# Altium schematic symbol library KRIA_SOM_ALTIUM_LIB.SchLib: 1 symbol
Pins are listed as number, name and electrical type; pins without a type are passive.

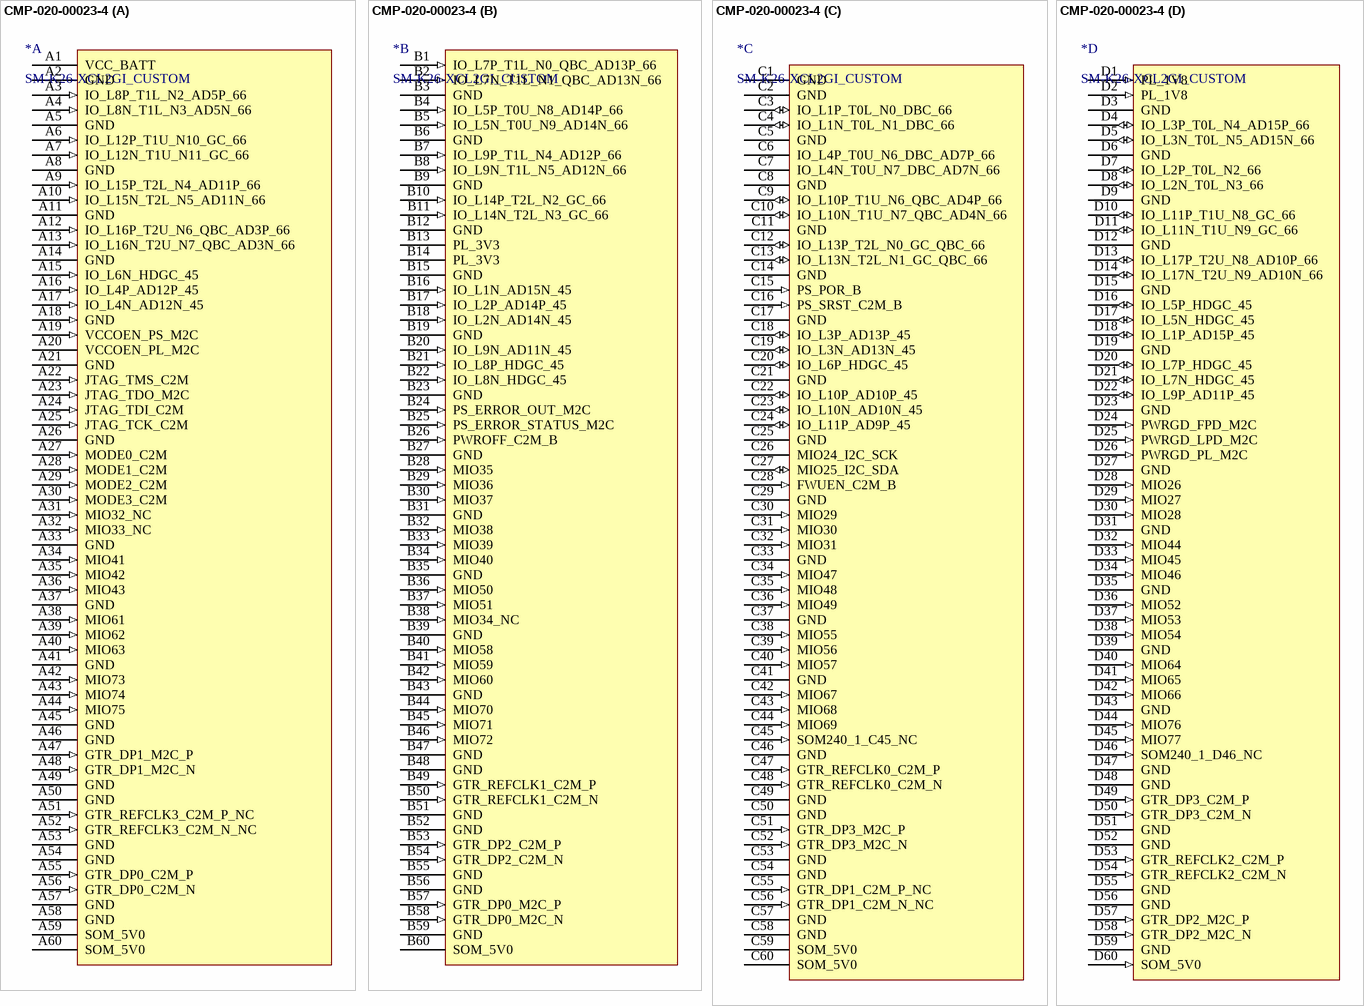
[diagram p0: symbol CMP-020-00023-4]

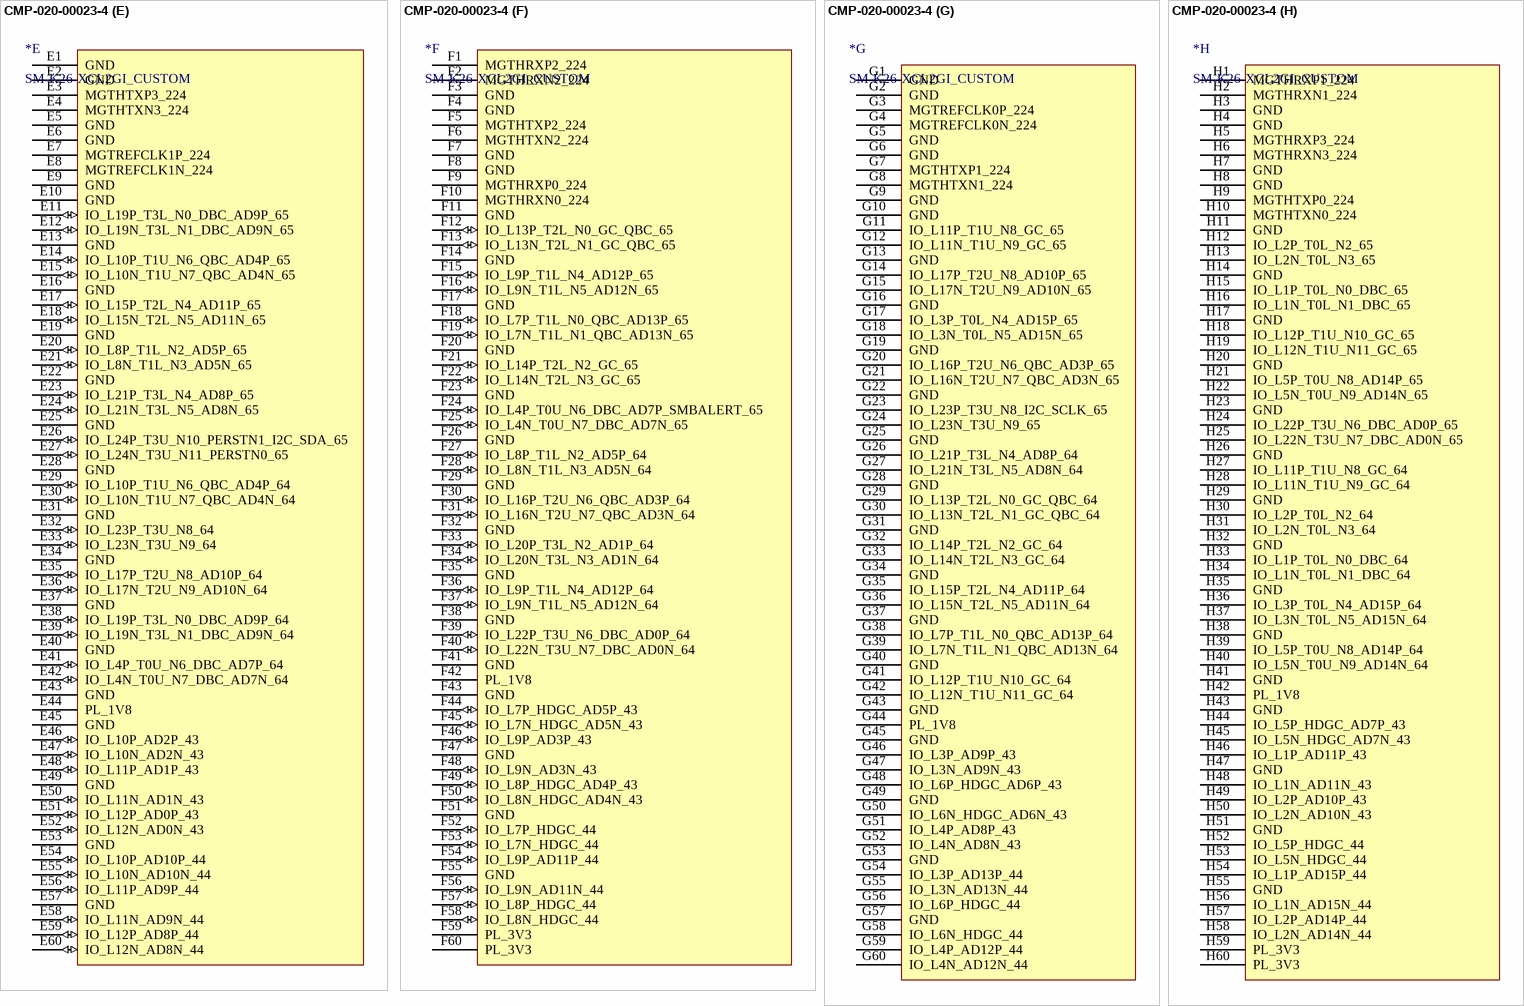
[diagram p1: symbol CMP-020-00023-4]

## CMP-020-00023-4
designator *, comment SM-K26-XCL2GI_CUSTOM
Zynq UltraScale Kria Embedded Module ARM Cortex-A53 Arm Cortex-R5F 533MHz, 1.333GHz 4GB 16GB eMMC, 64MB QSPI. Just the schematic is custom, Footprint already took from SnapMagic
footprint SM-K26-XCL2GI_CUSTOM-Footprint-1
part A pins: A1 VCC_BATT, A2 GND, A3 IO_L8P_T1L_N2_AD5P_66 (in), A4 IO_L8N_T1L_N3_AD5N_66 (in), A5 GND, A6 IO_L12P_T1U_N10_GC_66 (in), A7 IO_L12N_T1U_N11_GC_66 (in), A8 GND, A9 IO_L15P_T2L_N4_AD11P_66 (in), A10 IO_L15N_T2L_N5_AD11N_66 (in), A11 GND, A12 IO_L16P_T2U_N6_QBC_AD3P_66 (in), A13 IO_L16N_T2U_N7_QBC_AD3N_66 (in), A14 GND, A15 IO_L6N_HDGC_45 (in), A16 IO_L4P_AD12P_45 (in), A17 IO_L4N_AD12N_45 (in), A18 GND (in), A19 VCCOEN_PS_M2C (in), A20 VCCOEN_PL_M2C, A21 GND, A22 JTAG_TMS_C2M (in), A23 JTAG_TDO_M2C (in), A24 JTAG_TDI_C2M (in), A25 JTAG_TCK_C2M (in), A26 GND, A27 MODE0_C2M (in), A28 MODE1_C2M (in), A29 MODE2_C2M (in), A30 MODE3_C2M (in), A31 MIO32_NC (in), A32 MIO33_NC (in), A33 GND, A34 MIO41 (in), A35 MIO42 (in), A36 MIO43 (in), A37 GND, A38 MIO61 (in), A39 MIO62 (in), A40 MIO63 (in), A41 GND, A42 MIO73 (in), A43 MIO74 (in), A44 MIO75 (in), A45 GND, A46 GND, A47 GTR_DP1_M2C_P (in), A48 GTR_DP1_M2C_N (in), A49 GND, A50 GND, A51 GTR_REFCLK3_C2M_P_NC (in), A52 GTR_REFCLK3_C2M_N_NC (in), A53 GND, A54 GND, A55 GTR_DP0_C2M_P (in), A56 GTR_DP0_C2M_N (in), A57 GND, A58 GND, A59 SOM_5V0, A60 SOM_5V0
part B pins: B1 IO_L7P_T1L_N0_QBC_AD13P_66 (in), B2 IO_L7N_T1L_N1_QBC_AD13N_66 (in), B3 GND, B4 IO_L5P_T0U_N8_AD14P_66 (in), B5 IO_L5N_T0U_N9_AD14N_66 (in), B6 GND, B7 IO_L9P_T1L_N4_AD12P_66 (in), B8 IO_L9N_T1L_N5_AD12N_66 (in), B9 GND, B10 IO_L14P_T2L_N2_GC_66 (in), B11 IO_L14N_T2L_N3_GC_66 (in), B12 GND, B13 PL_3V3, B14 PL_3V3, B15 GND, B16 IO_L1N_AD15N_45 (in), B17 IO_L2P_AD14P_45 (in), B18 IO_L2N_AD14N_45 (in), B19 GND, B20 IO_L9N_AD11N_45 (in), B21 IO_L8P_HDGC_45 (in), B22 IO_L8N_HDGC_45 (in), B23 GND, B24 PS_ERROR_OUT_M2C (in), B25 PS_ERROR_STATUS_M2C (in), B26 PWROFF_C2M_B (in), B27 GND, B28 MIO35 (in), B29 MIO36 (in), B30 MIO37 (in), B31 GND, B32 MIO38 (in), B33 MIO39 (in), B34 MIO40 (in), B35 GND, B36 MIO50 (in), B37 MIO51 (in), B38 MIO34_NC (in), B39 GND, B40 MIO58 (in), B41 MIO59 (in), B42 MIO60 (in), B43 GND, B44 MIO70 (in), B45 MIO71 (in), B46 MIO72 (in), B47 GND, B48 GND, B49 GTR_REFCLK1_C2M_P (in), B50 GTR_REFCLK1_C2M_N (in), B51 GND, B52 GND, B53 GTR_DP2_C2M_P (in), B54 GTR_DP2_C2M_N (in), B55 GND, B56 GND, B57 GTR_DP0_M2C_P (in), B58 GTR_DP0_M2C_N (in), B59 GND, B60 SOM_5V0
part C pins: C1 GND, C2 GND, C3 IO_L1P_T0L_N0_DBC_66 (io), C4 IO_L1N_T0L_N1_DBC_66 (io), C5 GND, C6 IO_L4P_T0U_N6_DBC_AD7P_66, C7 IO_L4N_T0U_N7_DBC_AD7N_66, C8 GND, C9 IO_L10P_T1U_N6_QBC_AD4P_66 (io), C10 IO_L10N_T1U_N7_QBC_AD4N_66 (io), C11 GND, C12 IO_L13P_T2L_N0_GC_QBC_66 (io), C13 IO_L13N_T2L_N1_GC_QBC_66 (io), C14 GND, C15 PS_POR_B (in), C16 PS_SRST_C2M_B (in), C17 GND, C18 IO_L3P_AD13P_45 (io), C19 IO_L3N_AD13N_45 (io), C20 IO_L6P_HDGC_45 (io), C21 GND, C22 IO_L10P_AD10P_45 (io), C23 IO_L10N_AD10N_45 (io), C24 IO_L11P_AD9P_45 (io), C25 GND, C26 MIO24_I2C_SCK, C27 MIO25_I2C_SDA (io), C28 FWUEN_C2M_B (in), C29 GND, C30 MIO29 (in), C31 MIO30 (in), C32 MIO31 (in), C33 GND, C34 MIO47 (in), C35 MIO48 (in), C36 MIO49 (in), C37 GND, C38 MIO55 (in), C39 MIO56 (in), C40 MIO57 (in), C41 GND, C42 MIO67 (in), C43 MIO68 (in), C44 MIO69 (in), C45 SOM240_1_C45_NC (in), C46 GND, C47 GTR_REFCLK0_C2M_P (in), C48 GTR_REFCLK0_C2M_N (in), C49 GND, C50 GND, C51 GTR_DP3_M2C_P (in), C52 GTR_DP3_M2C_N (in), C53 GND, C54 GND, C55 GTR_DP1_C2M_P_NC (in), C56 GTR_DP1_C2M_N_NC (in), C57 GND, C58 GND, C59 SOM_5V0, C60 SOM_5V0
part D pins: D1 PL_1V8 (in), D2 PL_1V8 (in), D3 GND, D4 IO_L3P_T0L_N4_AD15P_66 (io), D5 IO_L3N_T0L_N5_AD15N_66 (io), D6 GND, D7 IO_L2P_T0L_N2_66 (io), D8 IO_L2N_T0L_N3_66 (io), D9 GND, D10 IO_L11P_T1U_N8_GC_66 (io), D11 IO_L11N_T1U_N9_GC_66 (io), D12 GND, D13 IO_L17P_T2U_N8_AD10P_66 (io), D14 IO_L17N_T2U_N9_AD10N_66 (io), D15 GND, D16 IO_L5P_HDGC_45 (io), D17 IO_L5N_HDGC_45 (io), D18 IO_L1P_AD15P_45 (io), D19 GND, D20 IO_L7P_HDGC_45 (io), D21 IO_L7N_HDGC_45 (io), D22 IO_L9P_AD11P_45 (io), D23 GND, D24 PWRGD_FPD_M2C (in), D25 PWRGD_LPD_M2C (in), D26 PWRGD_PL_M2C (in), D27 GND, D28 MIO26 (in), D29 MIO27 (in), D30 MIO28 (in), D31 GND, D32 MIO44 (in), D33 MIO45 (in), D34 MIO46 (in), D35 GND, D36 MIO52 (in), D37 MIO53 (in), D38 MIO54 (in), D39 GND, D40 MIO64 (in), D41 MIO65 (in), D42 MIO66 (in), D43 GND, D44 MIO76 (in), D45 MIO77 (in), D46 SOM240_1_D46_NC (in), D47 GND, D48 GND, D49 GTR_DP3_C2M_P (in), D50 GTR_DP3_C2M_N (in), D51 GND, D52 GND, D53 GTR_REFCLK2_C2M_P (in), D54 GTR_REFCLK2_C2M_N (in), D55 GND, D56 GND, D57 GTR_DP2_M2C_P (in), D58 GTR_DP2_M2C_N (in), D59 GND, D60 SOM_5V0 (in)
part E pins: E1 GND, E2 GND, E3 MGTHTXP3_224, E4 MGTHTXN3_224, E5 GND, E6 GND, E7 MGTREFCLK1P_224, E8 MGTREFCLK1N_224, E9 GND, E10 GND, E11 IO_L19P_T3L_N0_DBC_AD9P_65 (io), E12 IO_L19N_T3L_N1_DBC_AD9N_65 (io), E13 GND, E14 IO_L10P_T1U_N6_QBC_AD4P_65 (io), E15 IO_L10N_T1U_N7_QBC_AD4N_65 (io), E16 GND, E17 IO_L15P_T2L_N4_AD11P_65 (io), E18 IO_L15N_T2L_N5_AD11N_65 (io), E19 GND, E20 IO_L8P_T1L_N2_AD5P_65 (io), E21 IO_L8N_T1L_N3_AD5N_65 (io), E22 GND, E23 IO_L21P_T3L_N4_AD8P_65 (io), E24 IO_L21N_T3L_N5_AD8N_65 (io), E25 GND, E26 IO_L24P_T3U_N10_PERSTN1_I2C_SDA_65 (io), E27 IO_L24N_T3U_N11_PERSTN0_65 (io), E28 GND, E29 IO_L10P_T1U_N6_QBC_AD4P_64 (io), E30 IO_L10N_T1U_N7_QBC_AD4N_64 (io), E31 GND, E32 IO_L23P_T3U_N8_64 (io), E33 IO_L23N_T3U_N9_64 (io), E34 GND, E35 IO_L17P_T2U_N8_AD10P_64 (io), E36 IO_L17N_T2U_N9_AD10N_64 (io), E37 GND, E38 IO_L19P_T3L_N0_DBC_AD9P_64 (io), E39 IO_L19N_T3L_N1_DBC_AD9N_64 (io), E40 GND, E41 IO_L4P_T0U_N6_DBC_AD7P_64 (io), E42 IO_L4N_T0U_N7_DBC_AD7N_64 (io), E43 GND, E44 PL_1V8, E45 GND, E46 IO_L10P_AD2P_43 (io), E47 IO_L10N_AD2N_43 (io), E48 IO_L11P_AD1P_43 (io), E49 GND, E50 IO_L11N_AD1N_43 (io), E51 IO_L12P_AD0P_43 (io), E52 IO_L12N_AD0N_43 (io), E53 GND, E54 IO_L10P_AD10P_44 (io), E55 IO_L10N_AD10N_44 (io), E56 IO_L11P_AD9P_44 (io), E57 GND, E58 IO_L11N_AD9N_44 (io), E59 IO_L12P_AD8P_44 (io), E60 IO_L12N_AD8N_44 (io)
part F pins: F1 MGTHRXP2_224, F2 MGTHRXN2_224, F3 GND, F4 GND, F5 MGTHTXP2_224, F6 MGTHTXN2_224, F7 GND, F8 GND, F9 MGTHRXP0_224, F10 MGTHRXN0_224, F11 GND, F12 IO_L13P_T2L_N0_GC_QBC_65 (io), F13 IO_L13N_T2L_N1_GC_QBC_65 (io), F14 GND, F15 IO_L9P_T1L_N4_AD12P_65 (io), F16 IO_L9N_T1L_N5_AD12N_65 (io), F17 GND, F18 IO_L7P_T1L_N0_QBC_AD13P_65 (io), F19 IO_L7N_T1L_N1_QBC_AD13N_65 (io), F20 GND, F21 IO_L14P_T2L_N2_GC_65 (io), F22 IO_L14N_T2L_N3_GC_65 (io), F23 GND, F24 IO_L4P_T0U_N6_DBC_AD7P_SMBALERT_65 (io), F25 IO_L4N_T0U_N7_DBC_AD7N_65 (io), F26 GND, F27 IO_L8P_T1L_N2_AD5P_64 (io), F28 IO_L8N_T1L_N3_AD5N_64 (io), F29 GND, F30 IO_L16P_T2U_N6_QBC_AD3P_64 (io), F31 IO_L16N_T2U_N7_QBC_AD3N_64 (io), F32 GND, F33 IO_L20P_T3L_N2_AD1P_64 (io), F34 IO_L20N_T3L_N3_AD1N_64 (io), F35 GND, F36 IO_L9P_T1L_N4_AD12P_64 (io), F37 IO_L9N_T1L_N5_AD12N_64 (io), F38 GND, F39 IO_L22P_T3U_N6_DBC_AD0P_64 (io), F40 IO_L22N_T3U_N7_DBC_AD0N_64 (io), F41 GND, F42 PL_1V8, F43 GND, F44 IO_L7P_HDGC_AD5P_43 (io), F45 IO_L7N_HDGC_AD5N_43 (io), F46 IO_L9P_AD3P_43 (io), F47 GND, F48 IO_L9N_AD3N_43 (io), F49 IO_L8P_HDGC_AD4P_43 (io), F50 IO_L8N_HDGC_AD4N_43 (io), F51 GND, F52 IO_L7P_HDGC_44 (io), F53 IO_L7N_HDGC_44 (io), F54 IO_L9P_AD11P_44 (io), F55 GND, F56 IO_L9N_AD11N_44 (io), F57 IO_L8P_HDGC_44 (io), F58 IO_L8N_HDGC_44 (io), F59 PL_3V3, F60 PL_3V3
part G pins: G1 GND, G2 GND, G3 MGTREFCLK0P_224, G4 MGTREFCLK0N_224, G5 GND, G6 GND, G7 MGTHTXP1_224, G8 MGTHTXN1_224, G9 GND, G10 GND, G11 IO_L11P_T1U_N8_GC_65, G12 IO_L11N_T1U_N9_GC_65, G13 GND, G14 IO_L17P_T2U_N8_AD10P_65, G15 IO_L17N_T2U_N9_AD10N_65, G16 GND, G17 IO_L3P_T0L_N4_AD15P_65, G18 IO_L3N_T0L_N5_AD15N_65, G19 GND, G20 IO_L16P_T2U_N6_QBC_AD3P_65, G21 IO_L16N_T2U_N7_QBC_AD3N_65, G22 GND, G23 IO_L23P_T3U_N8_I2C_SCLK_65, G24 IO_L23N_T3U_N9_65, G25 GND, G26 IO_L21P_T3L_N4_AD8P_64, G27 IO_L21N_T3L_N5_AD8N_64, G28 GND, G29 IO_L13P_T2L_N0_GC_QBC_64, G30 IO_L13N_T2L_N1_GC_QBC_64, G31 GND, G32 IO_L14P_T2L_N2_GC_64, G33 IO_L14N_T2L_N3_GC_64, G34 GND, G35 IO_L15P_T2L_N4_AD11P_64, G36 IO_L15N_T2L_N5_AD11N_64, G37 GND, G38 IO_L7P_T1L_N0_QBC_AD13P_64, G39 IO_L7N_T1L_N1_QBC_AD13N_64, G40 GND, G41 IO_L12P_T1U_N10_GC_64, G42 IO_L12N_T1U_N11_GC_64, G43 GND, G44 PL_1V8, G45 GND, G46 IO_L3P_AD9P_43, G47 IO_L3N_AD9N_43, G48 IO_L6P_HDGC_AD6P_43, G49 GND, G50 IO_L6N_HDGC_AD6N_43, G51 IO_L4P_AD8P_43, G52 IO_L4N_AD8N_43, G53 GND, G54 IO_L3P_AD13P_44, G55 IO_L3N_AD13N_44, G56 IO_L6P_HDGC_44, G57 GND, G58 IO_L6N_HDGC_44, G59 IO_L4P_AD12P_44, G60 IO_L4N_AD12N_44
part H pins: H1 MGTHRXP1_224, H2 MGTHRXN1_224, H3 GND, H4 GND, H5 MGTHRXP3_224, H6 MGTHRXN3_224, H7 GND, H8 GND, H9 MGTHTXP0_224, H10 MGTHTXN0_224, H11 GND, H12 IO_L2P_T0L_N2_65, H13 IO_L2N_T0L_N3_65, H14 GND, H15 IO_L1P_T0L_N0_DBC_65, H16 IO_L1N_T0L_N1_DBC_65, H17 GND, H18 IO_L12P_T1U_N10_GC_65, H19 IO_L12N_T1U_N11_GC_65, H20 GND, H21 IO_L5P_T0U_N8_AD14P_65, H22 IO_L5N_T0U_N9_AD14N_65, H23 GND, H24 IO_L22P_T3U_N6_DBC_AD0P_65, H25 IO_L22N_T3U_N7_DBC_AD0N_65, H26 GND, H27 IO_L11P_T1U_N8_GC_64, H28 IO_L11N_T1U_N9_GC_64, H29 GND, H30 IO_L2P_T0L_N2_64, H31 IO_L2N_T0L_N3_64, H32 GND, H33 IO_L1P_T0L_N0_DBC_64, H34 IO_L1N_T0L_N1_DBC_64, H35 GND, H36 IO_L3P_T0L_N4_AD15P_64, H37 IO_L3N_T0L_N5_AD15N_64, H38 GND, H39 IO_L5P_T0U_N8_AD14P_64, H40 IO_L5N_T0U_N9_AD14N_64, H41 GND, H42 PL_1V8, H43 GND, H44 IO_L5P_HDGC_AD7P_43, H45 IO_L5N_HDGC_AD7N_43, H46 IO_L1P_AD11P_43, H47 GND, H48 IO_L1N_AD11N_43, H49 IO_L2P_AD10P_43, H50 IO_L2N_AD10N_43, H51 GND, H52 IO_L5P_HDGC_44, H53 IO_L5N_HDGC_44, H54 IO_L1P_AD15P_44, H55 GND, H56 IO_L1N_AD15N_44, H57 IO_L2P_AD14P_44, H58 IO_L2N_AD14N_44, H59 PL_3V3, H60 PL_3V3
